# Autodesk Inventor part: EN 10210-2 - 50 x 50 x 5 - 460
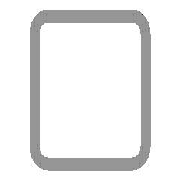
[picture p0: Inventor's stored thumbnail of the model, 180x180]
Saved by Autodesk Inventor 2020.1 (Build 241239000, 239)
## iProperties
_CCFamilyMember: 16
_CCFamilyDisplayName: DIN EN 10210-2 (USAS B17.1 quadratisch) - Rohrleitung — In Klammern angegebene Größen wurden aufgehoben
_FrameMemberDoc: Frame Member File
_Version: 15.0.0
_GetPNFromCC: 1
IsCustomPart: 1
Created: 2019-01
Part Number: EN 10210-2 - 50 x 50 x 5 - 460
Material: Stahl, weich
Description: Rohrleitung
Document SubType Name: Modeling
Standard: DIN
Designer: lutzd
Standard Revision: 2006-07
Standards Organization: DIN
Language: de-DE
Size Designation: 50 x 50 x 5
Categories: <MemberInstance><Categories><Category DisplayName="Profile" InternalName="089c4875-fa83-4c05-b084-43b9cc11f5ed" Mnemonic="GRDR"><CategoryParameter DisplayName="
Stock Number: 50 x 50 x 5
Mass: 3150.31 g
Surface Area: 1575.45 cm^2
Volume: 401.313 cm^3
Density: 7.85 g/cm^3
Appearance: Halbpoliert
G_L: 460,000 mm
G_W: 50,000 mm
G_H: 50,000 mm
DocNumber: ADSK-014083
Folder: .
Dimensions: 50x50x460 mm
Mass: 3,15 kg
+AE17E769-F210-48E2-BF37-B06E87CCFE5E+SCHNITTDETAIL1: Schnittwinkel 90,00 grd
Title: Profil-Bauteil
Author: lutzd
Revision Number: -
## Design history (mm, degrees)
node "Startebene"
node "Endebene"
sketch "Skizze"
  geometry: L1 (-25, -17.5)-(-25, 17.5); L2 (-17.5, 25)-(17.5, 25); L3 (25, 17.5)-(25, -17.5); L4 (17.5, -25)-(-17.5, -25); L5 (-15, 20)-(15, 20); L6 (20, 15)-(20, -15); L7 (15, -20)-(-15, -20); L8 (-20, -15)-(-20, 15); L9 (0, 37.175)-(0, -37.175) reference; L10 (-37.175, 0)-(37.175, 0) reference; A1 r 7.5 centre (-17.5, -17.5) between (-25, -17.5) and (-17.5, -25); A2 r 7.5 centre (-17.5, 17.5) between (-17.5, 25) and (-25, 17.5); A3 r 7.5 centre (17.5, 17.5) between (25, 17.5) and (17.5, 25); A4 r 7.5 centre (17.5, -17.5) between (17.5, -25) and (25, -17.5); A5 r 5 centre (-15, -15) between (-20, -15) and (-15, -20); A6 r 5 centre (-15, 15) between (-15, 20) and (-20, 15); A7 r 5 centre (15, 15) between (20, 15) and (15, 20); A8 r 5 centre (15, -15) between (15, -20) and (20, -15)
  constraints: 16 end point, 16 point on circle, 16 tangent, 8 centre point, 6 equal radius, 4 parallel, 2 perpendicular, 2 other
  dimensions: "d7" = 7.5 radius of A1 (= G_IR); "d10" = 50 distance between parallel lines of L2 L4 (= G_H); "d11" = 50 distance between parallel lines of L1 L3 (= G_W); "d12" = 5 distance between parallel lines of L3 L6 (= G_T); "d15" = 25 distance between parallel lines of L2 L10 (= 0.5 x d10); "d16" = 25 distance between parallel lines of L9 L3 (= 0.5 x d11); "d19" = 5 radius of A5 (= G_T); "d20" = 5 distance between parallel lines of L4 L7 (= G_T)
extrude "Körper" new body sketch "Skizze" stored distance "d3" = 460 (= G_L); taper "d4" = 0 deg
node "Driven Length"
  sketch "Sketch3"
    geometry: L1 (0, 0)-(10, 0) reference
    constraints: 2 end point, 1 horizontal
  workplane "Work Plane3"
  sketch "Sketch4"
    geometry: L1 (-2, 25)-(12, 25) reference; L2 (-2, 485)-(12, 485) reference
    dimensions: "d18" = 460 distance between parallel lines of L1 L2 (derived)
workplane "Arbeitsebene4"
feature "Trennen1"
sketch "Skizze5"
  geometry: L1 (0, -35)-(0, 0) reference; L2 (0, -17.5)-(321, -17.5); 3 further points
  constraints: 2 end point, 1 coincident, 1 horizontal, 1 midpoint, 1 point on line
  dimensions: "d21" = 41 distance of L2.end point (280, -17.5); "d22" = 280 distance from line of L1 point (280, -17.5)
hole "Bohrung1" sketch "Skizze5" at (321, -17.5), (280, -17.5) diameter "d23" = 6.647; stored, may be unused: countersink angle "d27" = 90 deg, drill point angle "d29" = 118 deg; dims "d24" = 16, "d25" = 4, "d26" = 2, "d28" = 8
body "Solid1"
other parameters: "G_W" = 50 [user parameter; used in 1 equation term], "G_H" = 50 [user parameter; used in 1 equation term], "G_T" = 5 [user parameter; used in 3 equation terms], "G_IR" = 7.5 [user parameter; used in 1 equation term], "G_L" = 460 (= d18) [user parameter; used in 1 equation term], "G_OFFSET_START" = -25 [user parameter; used in 1 equation term], "G_OFFSET_END" = 0 [user parameter; used in 1 equation term], "d13" = 25 (= -G_OFFSET_START), "d14" = 485 (= G_OFFSET_END + B_L), "B_L" = 485 [user parameter; used in 1 equation term], "d17" = 90 deg
